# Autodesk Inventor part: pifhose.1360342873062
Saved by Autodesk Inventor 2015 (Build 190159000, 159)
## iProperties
IsCustomPart: 1
Company: Parker Hannifin
Created: 2013-02
Material: Rubber
Description: Tömlő
Document SubType Name: Modeling
Standard: Parker
Designer: Marci
Manufacturer: Parker
Language: hu-HU
Size Designation: 1/4 - 5
Categories: <MemberInstance><Categories><Category DisplayName="Csővezetékek" InternalName="4347fa0f-2144-441d-94cd-e3e15c92b736" Mnemonic="TUBEANDPIPE"><CategoryParameter D
Stock Number: Parker hidraulikatömlő - No Skive 1/4
Density: 1 g/cm^3
Appearance: Rubber - Black - Version 1.1
NAME: PIPING: Parker Hydraulic Hose - No Skive
DATA: <meta><inlinegroups number="1" deflen="12.7"></inlinegroups><connections number="2"></connections><angles><a>3.14159265358979</a></angles></meta>
L: 21,101 in
PL: 21,101 in
RPL: 21,125 in
OPL: 21,101 in
ROPL: 21,125 in
Author: Marci
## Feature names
1. Sweep1
## Parameters: ID = 6.35 mm, OD = 14.986 mm, L = 535.9654 mm, PL = 535.9654 mm, Size_Designation = 2.5 mm, d6 = 0, RPL = 536.575 mm, OPL = 535.9654 mm, ROPL = 536.575 mm, d7 = 0
